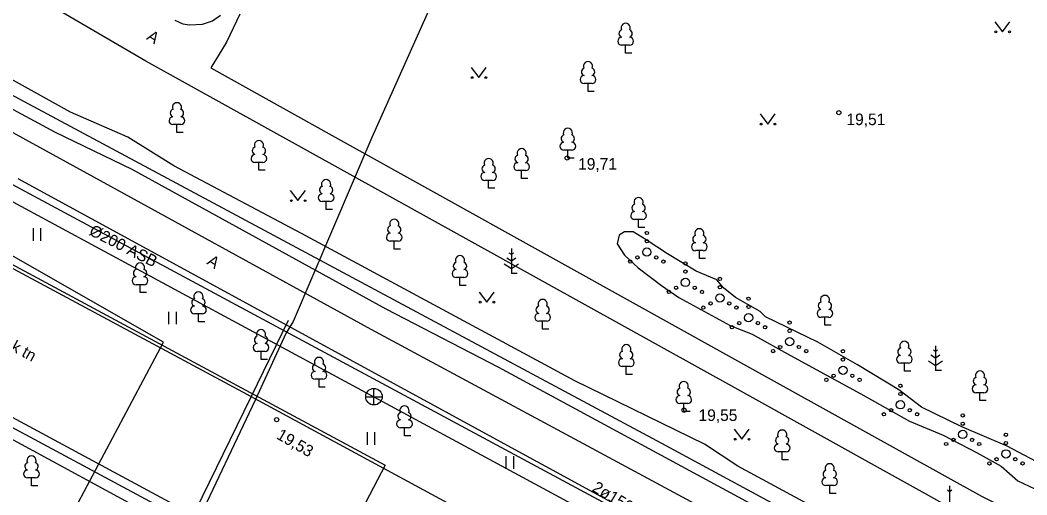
# Model space of a CAD drawing. Extents: x 713497 to 713863, y 6590062 to 6590327.
# Drawn here: x 713764.9 to 713825.7, y 6590158.5 to 6590187.1 of the extents above; entities that cross this region are included whole.
import ezdxf

# ---------------------------------------------------------------- set-up
doc = ezdxf.new("R2010")
doc.units = 0
for name, color, linetype in [('AED', 7, 'Continuous'), ('HALJASTUS', 7, 'Continuous'), ('HOONE', 7, 'Continuous'), ('KKAEV', 7, 'Continuous'), ('KORGUS', 7, 'Continuous'), ('KPKAABEL', 7, 'Continuous'), ('KTRASS', 7, 'Continuous'), ('MPKAABEL', 7, 'Continuous'), ('PUU', 7, 'Continuous'), ('SITRASS', 7, 'Continuous'), ('TEE', 7, 'Continuous'), ('TORU NR', 7, 'Continuous'), ('TTRASS', 7, 'Continuous')]:
    doc.layers.add(name, color=color, linetype=linetype)

msp = doc.modelspace()

# ---------------------------------------------------------------- linework, layer by layer
at = {"layer": 'AED'}
msp.add_lwpolyline([(713842.75, 6590140.44), (713835.11, 6590144.59), (713824.81, 6590150.12), (713803.9, 6590161.43), (713731.96, 6590199.96)], dxfattribs=at)
at = {"layer": 'HALJASTUS'}
for p, q in [((713823.747, 6590186.997), (713824.21, 6590186.39)), ((713824.21, 6590186.39), (713824.656, 6590186.997)), ((713792.127, 6590184.237), (713792.59, 6590183.63)), ((713792.59, 6590183.63), (713793.036, 6590184.237)), ((713809.577, 6590181.437), (713810.04, 6590180.83)), ((713810.04, 6590180.83), (713810.486, 6590181.437)), ((713781.217, 6590176.817), (713781.68, 6590176.21)), ((713781.68, 6590176.21), (713782.126, 6590176.817)), ((713765.686, 6590174.55), (713765.686, 6590173.789)), ((713766.141, 6590174.55), (713766.141, 6590173.789)), ((713792.617, 6590170.697), (713793.08, 6590170.09)), ((713793.08, 6590170.09), (713793.526, 6590170.697)), ((713773.862, 6590169.515), (713773.862, 6590168.754)), ((713774.317, 6590169.515), (713774.317, 6590168.754)), ((713808.017, 6590162.427), (713808.48, 6590161.82)), ((713808.48, 6590161.82), (713808.926, 6590162.427)), ((713785.85, 6590162.242), (713785.85, 6590161.481)), ((713786.305, 6590162.242), (713786.305, 6590161.481)), ((713794.233, 6590160.797), (713794.233, 6590160.036)), ((713794.688, 6590160.797), (713794.688, 6590160.036))]:
    msp.add_line(p, q, dxfattribs=at)
for points in [[(713841.26, 6590142.2), (713834.39, 6590145.82), (713823.52, 6590151.93), (713808.23, 6590160.2), (713806.22, 6590161.53), (713798.4, 6590165.35), (713781.9, 6590174.22), (713774.18, 6590178.32), (713771.41, 6590180.04), (713767.95, 6590181.54), (713761.08, 6590185.35), (713755.64, 6590188.21), (713751.36, 6590190.34), (713748.73, 6590191.96), (713741.58, 6590196.11), (713734, 6590200.4)], [(713732.19, 6590199.21), (713738.7, 6590195.69), (713747.61, 6590190.82), (713767.02, 6590180.35), (713771.65, 6590178.11), (713786.98, 6590169.69), (713793.79, 6590166.16), (713813.16, 6590155.69), (713817.55, 6590153.26), (713832.96, 6590144.79), (713835.16, 6590143.78), (713841.97, 6590140.16)], [(713805.71, 6590171.96), (713803.98, 6590173), (713802.69, 6590173.84), (713801.92, 6590174.33), (713801.4, 6590174.33), (713801.07, 6590174.13), (713800.95, 6590173.6), (713801.4, 6590172.92), (713802.21, 6590172.15), (713803.62, 6590171.1), (713804.67, 6590170.37), (713807.77, 6590168.68), (713809.1, 6590168.16), (713811.41, 6590166.87), (713815.65, 6590164.56), (713818.6, 6590162.91), (713820.62, 6590162.06), (713822.68, 6590161.01), (713824.13, 6590160.2), (713825.14, 6590159.31), (713826.84, 6590158.5)], [(713826.92, 6590160.12), (713824.5, 6590161.41), (713821.75, 6590162.58), (713819.32, 6590163.76), (713817.95, 6590164.81), (713815.45, 6590166.3), (713813.06, 6590167.67), (713809.91, 6590169.21), (713809.59, 6590169.53), (713808.09, 6590170.38), (713807.37, 6590170.95), (713806.96, 6590171.43), (713805.71, 6590171.96)]]:
    msp.add_lwpolyline(points, dxfattribs=at)
for centre, radius in [((713823.809, 6590186.39), 0.055), ((713824.638, 6590186.39), 0.055), ((713792.189, 6590183.63), 0.055), ((713793.018, 6590183.63), 0.055), ((713809.639, 6590180.83), 0.055), ((713810.468, 6590180.83), 0.055), ((713781.279, 6590176.21), 0.055), ((713782.108, 6590176.21), 0.055), ((713802.74, 6590174.26), 0.1), ((713802.74, 6590173.76), 0.1), ((713802.74, 6590173.11), 0.25), ((713801.74, 6590172.535), 0.1), ((713802.175, 6590172.785), 0.1), ((713803.305, 6590172.785), 0.1), ((713803.74, 6590172.535), 0.1), ((713805.07, 6590172.43), 0.1), ((713805.07, 6590171.93), 0.1), ((713805.07, 6590171.28), 0.25), ((713807.15, 6590171.49), 0.1), ((713804.07, 6590170.705), 0.1), ((713804.505, 6590170.955), 0.1), ((713805.635, 6590170.955), 0.1), ((713806.07, 6590170.705), 0.1), ((713807.15, 6590170.99), 0.1), ((713807.15, 6590170.34), 0.25), ((713808.88, 6590170.3), 0.1), ((713792.679, 6590170.09), 0.055), ((713793.508, 6590170.09), 0.055), ((713806.15, 6590169.765), 0.1), ((713806.585, 6590170.015), 0.1), ((713807.715, 6590170.015), 0.1), ((713808.15, 6590169.765), 0.1), ((713808.88, 6590169.8), 0.1), ((713808.88, 6590169.15), 0.25), ((713811.36, 6590168.86), 0.1), ((713807.88, 6590168.575), 0.1), ((713808.315, 6590168.825), 0.1), ((713809.445, 6590168.825), 0.1), ((713809.88, 6590168.575), 0.1), ((713811.36, 6590168.36), 0.1), ((713811.36, 6590167.71), 0.25), ((713810.36, 6590167.135), 0.1), ((713810.795, 6590167.385), 0.1), ((713811.925, 6590167.385), 0.1), ((713812.36, 6590167.135), 0.1), ((713814.58, 6590167.13), 0.1), ((713814.58, 6590166.63), 0.1), ((713814.58, 6590165.98), 0.25), ((713813.58, 6590165.405), 0.1), ((713814.015, 6590165.655), 0.1), ((713815.145, 6590165.655), 0.1), ((713815.58, 6590165.405), 0.1), ((713818.05, 6590165.05), 0.1), ((713818.05, 6590163.9), 0.25), ((713818.05, 6590164.55), 0.1), ((713817.485, 6590163.575), 0.1), ((713818.615, 6590163.575), 0.1), ((713817.05, 6590163.325), 0.1), ((713819.05, 6590163.325), 0.1), ((713821.81, 6590163.26), 0.1), ((713821.81, 6590162.76), 0.1), ((713821.81, 6590162.11), 0.25), ((713808.079, 6590161.82), 0.055), ((713808.908, 6590161.82), 0.055), ((713821.245, 6590161.785), 0.1), ((713822.375, 6590161.785), 0.1), ((713824.42, 6590162.09), 0.1), ((713824.42, 6590161.59), 0.1), ((713820.81, 6590161.535), 0.1), ((713822.81, 6590161.535), 0.1), ((713824.42, 6590160.94), 0.25), ((713823.42, 6590160.365), 0.1), ((713823.855, 6590160.615), 0.1), ((713824.985, 6590160.615), 0.1), ((713825.42, 6590160.365), 0.1)]:
    msp.add_circle(centre, radius, dxfattribs=at)
at = {"layer": 'HOONE'}
msp.add_lwpolyline([(713734.713, 6590179.152), (713785.66, 6590151.72), (713826.27, 6590130.08), (713863.358, 6590110.159)], dxfattribs=at)
at = {"layer": 'KKAEV'}
for p, q in [((713786.266, 6590163.888), (713786.266, 6590164.888)), ((713785.766, 6590164.388), (713786.766, 6590164.388))]:
    msp.add_line(p, q, dxfattribs=at)
msp.add_circle((713786.266, 6590164.388), 0.5, dxfattribs=at)
at = {"layer": 'KORGUS'}
for centre in [(713814.33, 6590181.52), (713797.93, 6590178.78), (713804.98, 6590163.58), (713780.39, 6590163)]:
    msp.add_circle(centre, 0.125, dxfattribs=at)
at = {"layer": 'KPKAABEL'}
for points in [[(713529.988, 6590287.362), (713528.13, 6590283.39), (713562.908, 6590269.342), (713609.57, 6590248.393), (713642.834, 6590233.164), (713665.543, 6590222.669), (713703.801, 6590203.145), (713710.007, 6590200.019), (713735.256, 6590187.298), (713757.247, 6590176.218), (713786.95, 6590160.25), (713778.485, 6590144.103)], [(713794.45, 6590198.59), (713786.13, 6590180.02), (713781.379, 6590168.923), (713780.962, 6590168.239), (713779.091, 6590164.176), (713775.448, 6590156.503), (713774.002, 6590151.688), (713770.408, 6590144.999), (713769.646, 6590143.487), (713765.21, 6590132.86), (713761.14, 6590113.48)]]:
    msp.add_lwpolyline(points, dxfattribs=at)
at = {"layer": 'KTRASS'}
for points in [[(713758.663, 6590179.261), (713786.266, 6590164.388)], [(713786.266, 6590164.388), (713813.145, 6590149.856)]]:
    msp.add_lwpolyline(points, dxfattribs=at)
at = {"layer": 'MPKAABEL'}
for points in [[(713831.772, 6590125.699), (713828.625, 6590127.375), (713802.947, 6590141.184), (713775.431, 6590155.836), (713748.262, 6590170.579), (713743.764, 6590161.693), (713741.527, 6590162.242)], [(713781.077, 6590168.981), (713778.842, 6590164.352), (713775.042, 6590156.623), (713771.019, 6590147.665), (713770.454, 6590144.893), (713769.354, 6590143.636), (713766.17, 6590138.15), (713788.39, 6590122.43), (713799.07, 6590115.1), (713794.37, 6590106.34), (713776.17, 6590073.19)]]:
    msp.add_lwpolyline(points, dxfattribs=at)
at = {"layer": 'PUU'}
for p, q in [((713801.7, 6590185.585), (713801.22, 6590185.585)), ((713801.46, 6590185.11), (713801.46, 6590185.585)), ((713801.84, 6590185.11), (713801.46, 6590185.11)), ((713799.43, 6590183.275), (713798.95, 6590183.275)), ((713799.19, 6590182.8), (713799.19, 6590183.275)), ((713799.57, 6590182.8), (713799.19, 6590182.8)), ((713774.61, 6590180.795), (713774.13, 6590180.795)), ((713774.37, 6590180.32), (713774.37, 6590180.795)), ((713774.75, 6590180.32), (713774.37, 6590180.32)), ((713798.21, 6590179.255), (713797.73, 6590179.255)), ((713797.97, 6590178.78), (713797.97, 6590179.255)), ((713798.35, 6590178.78), (713797.97, 6590178.78)), ((713779.56, 6590178.515), (713779.08, 6590178.515)), ((713779.32, 6590178.04), (713779.32, 6590178.515)), ((713779.7, 6590178.04), (713779.32, 6590178.04)), ((713795.42, 6590178.025), (713794.94, 6590178.025)), ((713795.18, 6590177.55), (713795.18, 6590178.025)), ((713795.56, 6590177.55), (713795.18, 6590177.55)), ((713793.43, 6590177.435), (713792.95, 6590177.435)), ((713793.19, 6590176.96), (713793.19, 6590177.435)), ((713793.57, 6590176.96), (713793.19, 6590176.96)), ((713783.62, 6590176.155), (713783.14, 6590176.155)), ((713783.38, 6590175.68), (713783.38, 6590176.155)), ((713783.76, 6590175.68), (713783.38, 6590175.68)), ((713802.48, 6590175.075), (713802, 6590175.075)), ((713802.24, 6590174.6), (713802.24, 6590175.075)), ((713802.62, 6590174.6), (713802.24, 6590174.6)), ((713787.73, 6590173.765), (713787.25, 6590173.765)), ((713787.49, 6590173.29), (713787.49, 6590173.765)), ((713787.87, 6590173.29), (713787.49, 6590173.29)), ((713794.56, 6590173.32), (713794.56, 6590171.82)), ((713806.15, 6590173.195), (713805.67, 6590173.195)), ((713805.91, 6590172.72), (713805.91, 6590173.195)), ((713794.56, 6590172.57), (713794.293, 6590172.748)), ((713794.56, 6590172.97), (713794.436, 6590173.053)), ((713794.684, 6590173.053), (713794.56, 6590172.97)), ((713794.827, 6590172.748), (713794.56, 6590172.57)), ((713806.29, 6590172.72), (713805.91, 6590172.72)), ((713794.136, 6590172.409), (713794.56, 6590172.127)), ((713794.56, 6590172.127), (713794.984, 6590172.409)), ((713791.7, 6590171.575), (713791.22, 6590171.575)), ((713791.46, 6590171.1), (713791.46, 6590171.575)), ((713794.92, 6590171.82), (713794.56, 6590171.82)), ((713772.385, 6590171.142), (713771.905, 6590171.142)), ((713772.145, 6590170.667), (713772.145, 6590171.142)), ((713791.84, 6590171.1), (713791.46, 6590171.1)), ((713772.525, 6590170.667), (713772.145, 6590170.667)), ((713775.911, 6590169.38), (713775.431, 6590169.38)), ((713775.671, 6590168.905), (713775.671, 6590169.38)), ((713796.69, 6590168.935), (713796.21, 6590168.935)), ((713796.45, 6590168.46), (713796.45, 6590168.935)), ((713813.73, 6590169.175), (713813.25, 6590169.175)), ((713813.49, 6590168.7), (713813.49, 6590169.175)), ((713776.051, 6590168.905), (713775.671, 6590168.905)), ((713796.83, 6590168.46), (713796.45, 6590168.46)), ((713813.87, 6590168.7), (713813.49, 6590168.7)), ((713779.691, 6590167.116), (713779.211, 6590167.116)), ((713779.451, 6590166.641), (713779.451, 6590167.116)), ((713820.16, 6590167.11), (713820.036, 6590167.193)), ((713820.16, 6590167.46), (713820.16, 6590165.96)), ((713820.284, 6590167.193), (713820.16, 6590167.11)), ((713779.831, 6590166.641), (713779.451, 6590166.641)), ((713819.736, 6590166.549), (713820.16, 6590166.267)), ((713820.16, 6590166.71), (713819.893, 6590166.888)), ((713820.427, 6590166.888), (713820.16, 6590166.71)), ((713820.16, 6590166.267), (713820.584, 6590166.549)), ((713801.74, 6590166.205), (713801.26, 6590166.205)), ((713801.5, 6590165.73), (713801.5, 6590166.205)), ((713818.53, 6590166.405), (713818.05, 6590166.405)), ((713818.29, 6590165.93), (713818.29, 6590166.405)), ((713818.67, 6590165.93), (713818.29, 6590165.93)), ((713820.52, 6590165.96), (713820.16, 6590165.96)), ((713783.189, 6590165.437), (713782.709, 6590165.437)), ((713782.949, 6590164.962), (713782.949, 6590165.437)), ((713801.88, 6590165.73), (713801.5, 6590165.73)), ((713783.329, 6590164.962), (713782.949, 6590164.962)), ((713823.09, 6590164.625), (713822.61, 6590164.625)), ((713822.85, 6590164.15), (713822.85, 6590164.625)), ((713823.23, 6590164.15), (713822.85, 6590164.15)), ((713805.21, 6590163.975), (713804.73, 6590163.975)), ((713804.97, 6590163.5), (713804.97, 6590163.975)), ((713805.35, 6590163.5), (713804.97, 6590163.5)), ((713788.349, 6590162.512), (713787.869, 6590162.512)), ((713788.109, 6590162.037), (713788.109, 6590162.512)), ((713788.489, 6590162.037), (713788.109, 6590162.037)), ((713811.15, 6590161.055), (713810.67, 6590161.055)), ((713810.91, 6590160.58), (713810.91, 6590161.055)), ((713811.29, 6590160.58), (713810.91, 6590160.58)), ((713765.832, 6590159.49), (713765.352, 6590159.49)), ((713765.592, 6590159.015), (713765.592, 6590159.49)), ((713765.972, 6590159.015), (713765.592, 6590159.015)), ((713814.02, 6590159.025), (713813.54, 6590159.025)), ((713813.78, 6590158.55), (713813.78, 6590159.025)), ((713821.02, 6590158.66), (713820.896, 6590158.743)), ((713821.02, 6590159.01), (713821.02, 6590157.51)), ((713821.144, 6590158.743), (713821.02, 6590158.66)), ((713814.16, 6590158.55), (713813.78, 6590158.55))]:
    msp.add_line(p, q, dxfattribs=at)
for centre, radius, start, end in [((713801.46, 6590186.63), 0.277, 332.5799, 207.4201), ((713801.223, 6590185.822), 0.238, 90.0016, 269.3953), ((713801.29, 6590186.283), 0.233, 109.02174, 253.14154), ((713801.63, 6590186.283), 0.233, 286.85082, 70.98591), ((713801.697, 6590185.822), 0.238, 270.6047, 89.9984), ((713799.02, 6590183.973), 0.233, 109.02174, 253.14154), ((713799.19, 6590184.32), 0.277, 332.5799, 207.4201), ((713799.36, 6590183.973), 0.233, 286.85082, 70.98591), ((713798.953, 6590183.512), 0.238, 90.0016, 269.3953), ((713799.427, 6590183.512), 0.238, 270.6047, 89.9984), ((713774.2, 6590181.493), 0.233, 109.02174, 253.14154), ((713774.37, 6590181.84), 0.277, 332.5799, 207.4201), ((713774.54, 6590181.493), 0.233, 286.85082, 70.98591), ((713774.133, 6590181.032), 0.238, 90.0016, 269.3953), ((713774.607, 6590181.032), 0.238, 270.6047, 89.9984), ((713797.97, 6590180.3), 0.277, 332.5799, 207.4201), ((713797.8, 6590179.953), 0.233, 109.02174, 253.14154), ((713798.14, 6590179.953), 0.233, 286.85082, 70.98591), ((713779.15, 6590179.213), 0.233, 109.02174, 253.14154), ((713779.32, 6590179.56), 0.277, 332.5799, 207.4201), ((713779.49, 6590179.213), 0.233, 286.85082, 70.98591), ((713795.18, 6590179.07), 0.277, 332.5799, 207.4201), ((713797.733, 6590179.492), 0.238, 90.0016, 269.3953), ((713798.207, 6590179.492), 0.238, 270.6047, 89.9984), ((713779.083, 6590178.752), 0.238, 90.0016, 269.3953), ((713779.557, 6590178.752), 0.238, 270.6047, 89.9984), ((713793.19, 6590178.48), 0.277, 332.5799, 207.4201), ((713795.01, 6590178.723), 0.233, 109.02174, 253.14154), ((713795.35, 6590178.723), 0.233, 286.85082, 70.98591), ((713793.02, 6590178.133), 0.233, 109.02174, 253.14154), ((713793.36, 6590178.133), 0.233, 286.85082, 70.98591), ((713794.943, 6590178.262), 0.238, 90.0016, 269.3953), ((713795.417, 6590178.262), 0.238, 270.6047, 89.9984), ((713783.38, 6590177.2), 0.277, 332.5799, 207.4201), ((713792.953, 6590177.672), 0.238, 90.0016, 269.3953), ((713793.427, 6590177.672), 0.238, 270.6047, 89.9984), ((713783.21, 6590176.853), 0.233, 109.02174, 253.14154), ((713783.55, 6590176.853), 0.233, 286.85082, 70.98591), ((713783.143, 6590176.392), 0.238, 90.0016, 269.3953), ((713783.617, 6590176.392), 0.238, 270.6047, 89.9984), ((713802.24, 6590176.12), 0.277, 332.5799, 207.4201), ((713802.07, 6590175.773), 0.233, 109.02174, 253.14154), ((713802.41, 6590175.773), 0.233, 286.85082, 70.98591), ((713787.49, 6590174.81), 0.277, 332.5799, 207.4201), ((713802.003, 6590175.312), 0.238, 90.0016, 269.3953), ((713802.477, 6590175.312), 0.238, 270.6047, 89.9984), ((713787.32, 6590174.463), 0.233, 109.02174, 253.14154), ((713787.66, 6590174.463), 0.233, 286.85082, 70.98591), ((713805.91, 6590174.24), 0.277, 332.5799, 207.4201), ((713787.253, 6590174.002), 0.238, 90.0016, 269.3953), ((713787.727, 6590174.002), 0.238, 270.6047, 89.9984), ((713805.74, 6590173.893), 0.233, 109.02174, 253.14154), ((713806.08, 6590173.893), 0.233, 286.85082, 70.98591), ((713805.673, 6590173.432), 0.238, 90.0016, 269.3953), ((713806.147, 6590173.432), 0.238, 270.6047, 89.9984), ((713791.46, 6590172.62), 0.277, 332.5799, 207.4201), ((713771.975, 6590171.84), 0.233, 109.02174, 253.14154), ((713772.145, 6590172.187), 0.277, 332.5799, 207.4201), ((713772.315, 6590171.84), 0.233, 286.85082, 70.98591), ((713791.223, 6590171.812), 0.238, 90.0016, 269.3953), ((713791.29, 6590172.273), 0.233, 109.02174, 253.14154), ((713791.63, 6590172.273), 0.233, 286.85082, 70.98591), ((713791.697, 6590171.812), 0.238, 270.6047, 89.9984), ((713771.907, 6590171.379), 0.238, 90.0016, 269.3953), ((713772.382, 6590171.379), 0.238, 270.6047, 89.9984), ((713775.5, 6590170.078), 0.233, 109.02174, 253.14154), ((713775.671, 6590170.425), 0.277, 332.5799, 207.4201), ((713775.841, 6590170.078), 0.233, 286.85082, 70.98591), ((713796.45, 6590169.98), 0.277, 332.5799, 207.4201), ((713813.49, 6590170.22), 0.277, 332.5799, 207.4201), ((713775.433, 6590169.617), 0.238, 90.0016, 269.3953), ((713775.908, 6590169.617), 0.238, 270.6047, 89.9984), ((713796.28, 6590169.633), 0.233, 109.02174, 253.14154), ((713796.62, 6590169.633), 0.233, 286.85082, 70.98591), ((713813.253, 6590169.412), 0.238, 90.0016, 269.3953), ((713813.32, 6590169.873), 0.233, 109.02174, 253.14154), ((713813.66, 6590169.873), 0.233, 286.85082, 70.98591), ((713813.727, 6590169.412), 0.238, 270.6047, 89.9984), ((713796.213, 6590169.172), 0.238, 90.0016, 269.3953), ((713796.687, 6590169.172), 0.238, 270.6047, 89.9984), ((713779.451, 6590168.161), 0.277, 332.5799, 207.4201), ((713779.281, 6590167.814), 0.233, 109.02174, 253.14154), ((713779.621, 6590167.814), 0.233, 286.85082, 70.98591), ((713818.29, 6590167.45), 0.277, 332.5799, 207.4201), ((713779.214, 6590167.354), 0.238, 90.0016, 269.3953), ((713779.689, 6590167.354), 0.238, 270.6047, 89.9984), ((713801.33, 6590166.903), 0.233, 109.02174, 253.14154), ((713801.5, 6590167.25), 0.277, 332.5799, 207.4201), ((713801.67, 6590166.903), 0.233, 286.85082, 70.98591), ((713818.12, 6590167.103), 0.233, 109.02174, 253.14154), ((713818.46, 6590167.103), 0.233, 286.85082, 70.98591), ((713782.949, 6590166.482), 0.277, 332.5799, 207.4201), ((713801.263, 6590166.442), 0.238, 90.0016, 269.3953), ((713801.737, 6590166.442), 0.238, 270.6047, 89.9984), ((713818.053, 6590166.642), 0.238, 90.0016, 269.3953), ((713818.527, 6590166.642), 0.238, 270.6047, 89.9984), ((713782.712, 6590165.675), 0.238, 90.0016, 269.3953), ((713782.779, 6590166.135), 0.233, 109.02174, 253.14154), ((713783.119, 6590166.135), 0.233, 286.85082, 70.98591), ((713783.187, 6590165.675), 0.238, 270.6047, 89.9984), ((713822.85, 6590165.67), 0.277, 332.5799, 207.4201), ((713804.97, 6590165.02), 0.277, 332.5799, 207.4201), ((713822.68, 6590165.323), 0.233, 109.02174, 253.14154), ((713823.02, 6590165.323), 0.233, 286.85082, 70.98591), ((713804.8, 6590164.673), 0.233, 109.02174, 253.14154), ((713805.14, 6590164.673), 0.233, 286.85082, 70.98591), ((713822.613, 6590164.862), 0.238, 90.0016, 269.3953), ((713823.087, 6590164.862), 0.238, 270.6047, 89.9984), ((713804.733, 6590164.212), 0.238, 90.0016, 269.3953), ((713805.207, 6590164.212), 0.238, 270.6047, 89.9984), ((713788.109, 6590163.557), 0.277, 332.5799, 207.4201), ((713787.871, 6590162.749), 0.238, 90.0016, 269.3953), ((713787.939, 6590163.209), 0.233, 109.02174, 253.14154), ((713788.279, 6590163.209), 0.233, 286.85082, 70.98591), ((713788.346, 6590162.749), 0.238, 270.6047, 89.9984), ((713810.91, 6590162.1), 0.277, 332.5799, 207.4201), ((713810.74, 6590161.753), 0.233, 109.02174, 253.14154), ((713811.08, 6590161.753), 0.233, 286.85082, 70.98591), ((713810.673, 6590161.292), 0.238, 90.0016, 269.3953), ((713811.147, 6590161.292), 0.238, 270.6047, 89.9984), ((713765.592, 6590160.535), 0.277, 332.5799, 207.4201), ((713765.355, 6590159.728), 0.238, 90.0016, 269.3953), ((713765.422, 6590160.188), 0.233, 109.02174, 253.14154), ((713765.763, 6590160.188), 0.233, 286.85082, 70.98591), ((713765.83, 6590159.728), 0.238, 270.6047, 89.9984), ((713813.61, 6590159.723), 0.233, 109.02174, 253.14154), ((713813.78, 6590160.07), 0.277, 332.5799, 207.4201), ((713813.95, 6590159.723), 0.233, 286.85082, 70.98591), ((713813.543, 6590159.262), 0.238, 90.0016, 269.3953), ((713814.017, 6590159.262), 0.238, 270.6047, 89.9984)]:
    msp.add_arc(centre, radius, start, end, dxfattribs=at)
at = {"layer": 'SITRASS'}
msp.add_lwpolyline([(713761.318, 6590146.366), (713762.03, 6590146.03), (713762.599, 6590147.099), (713773.56, 6590167.68), (713757.589, 6590176.783), (713720.92, 6590195.235), (713722.942, 6590199.176), (713727.49, 6590208.04), (713727.52, 6590208.2), (713727.47, 6590208.33), (713725.65, 6590209.17)], dxfattribs=at)
at = {"layer": 'TEE'}
for points in [[(713844.05, 6590146.1), (713839.66, 6590148.3), (713822.24, 6590157.05), (713808.23, 6590164.82), (713794.22, 6590172.59), (713772.5, 6590184.62), (713759.78, 6590192.031), (713751.212, 6590196.696), (713745.898, 6590199.593), (713737.505, 6590202.852), (713737.134, 6590202.824), (713736.264, 6590202.76), (713735.329, 6590202.691), (713734.382, 6590202.621), (713732.876, 6590202.51)], [(713731.142, 6590198.62), (713786.08, 6590168.47), (713841.45, 6590138.66), (713842.3, 6590139.86), (713843.54, 6590141.68), (713844.35, 6590143.09), (713844.47, 6590143.68), (713844.53, 6590144.74), (713844.05, 6590146.1)], [(713729.503, 6590195.962), (713814.96, 6590150.045), (713845.029, 6590133.836), (713845.889, 6590131.902), (713844.472, 6590129.05), (713816.858, 6590143.891), (713797.519, 6590154.285), (713778.342, 6590164.655), (713757.415, 6590175.881), (713740.491, 6590185.02), (713731.812, 6590189.692)], [(713774.24, 6590187.1), (713774.72, 6590186.88), (713775.14, 6590186.81), (713775.91, 6590186.86), (713776.51, 6590187.06), (713777, 6590187.39)], [(713778.16, 6590187.46), (713777.37, 6590185.76), (713776.41, 6590184.22), (713783.74, 6590180.13), (713808.94, 6590166.14), (713822.94, 6590158.38), (713840.33, 6590149.64), (713846.95, 6590146.33), (713847.17, 6590146.21), (713847.63, 6590146.19), (713848.09, 6590146.29), (713851.07, 6590148.45), (713854.06, 6590150.61), (713856.04, 6590152.38), (713858.02, 6590154.16), (713858.23, 6590154.37), (713859, 6590155.45), (713860.46, 6590157.83), (713861.92, 6590160.21), (713863.06, 6590162.07), (713863.358, 6590162.46)], [(713828.341, 6590128.138), (713812.872, 6590136.509), (713793.453, 6590146.972), (713774.088, 6590157.345), (713753.397, 6590168.434), (713735.495, 6590177.892), (713731.587, 6590178.663), (713718.885, 6590185.577)]]:
    msp.add_lwpolyline(points, dxfattribs=at)
at = {"layer": 'TTRASS'}
msp.add_lwpolyline([(713764.762, 6590177.546), (713819.5, 6590147.74), (713838.59, 6590137.39), (713838.728, 6590137.664)], dxfattribs=at)

# ---------------------------------------------------------------- texts
at = {"layer": 'KORGUS'}
for s, p in [('19,51', (713814.792, 6590180.765)), ('19,71', (713798.592, 6590178.075)), ('19,55', (713805.863, 6590162.925))]:
    msp.add_text(s, height=0.7, dxfattribs=at).set_placement(p)
msp.add_text('19,53', height=0.7, rotation=329.83719, dxfattribs=at).set_placement((713780.326, 6590161.893))
at = {"layer": 'KTRASS'}
msp.add_text('%%c200 ASB', height=0.7, rotation=333.09479, dxfattribs=at).set_placement((713769.017, 6590174.179))
at = {"layer": 'TEE'}
for s, rotation, p in [('A', 327.10115, (713772.492, 6590185.963)), ('A', 327.10115, (713776.132, 6590172.413)), ('Kesk tn', 331.38135, (713762.895, 6590167.976))]:
    msp.add_text(s, height=0.7, rotation=rotation, dxfattribs=at).set_placement(p)
at = {"layer": 'TORU NR'}
msp.add_text('2ø150', height=0.7, rotation=328.98555, dxfattribs=at).set_placement((713799.389, 6590158.733))

doc.saveas('drawing.dxf')
